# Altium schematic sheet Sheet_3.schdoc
size 307 x 219 mm
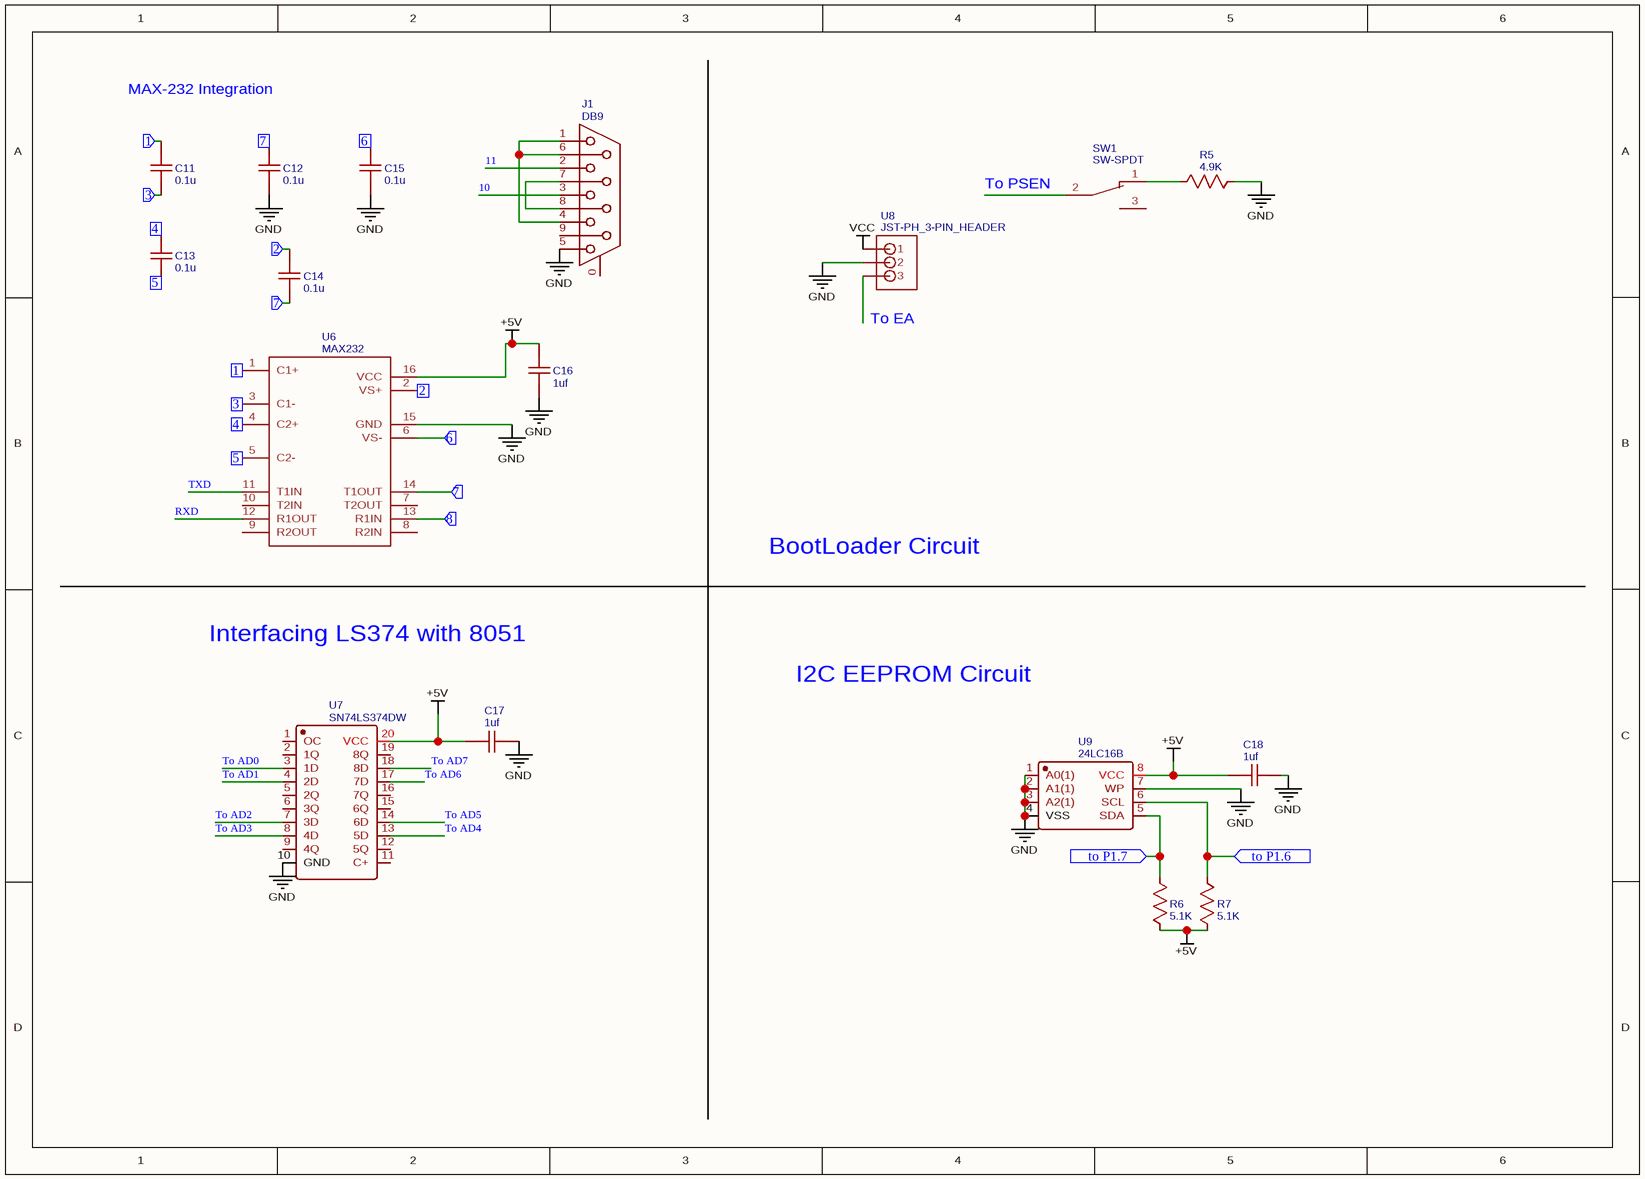
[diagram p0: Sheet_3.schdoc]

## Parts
C11  0.1u  [C0603]
C12  0.1u  [C0603]
C13  0.1u  [C0603]
C14  0.1u  [C0603]
C15  0.1u  [C0603]
C16  1uf  [C0603]
C17  1uf  [C0603]
C18  1uf  [C0603]
J1  DB9
R5  4.9K  [R0603]
R6  5.1K  [R0603]
R7  5.1K  [R0603]
SW1  SW-SPDT  [SW-SPDT-]
U6  MAX232
U7  SN74LS374DW  [SOIC-20]
U8  JST-PH_3-PIN_HEADER  [JST_B3B-PH_HEADER]
U9  24LC16B  [TSSOP-8_L4.4-W3.0-P0.65-LS6.4-BL]

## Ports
1 (in), 2 (in), 3 (in), 4 (in), 5 (in), 6 (in), 7 (in), 8 (in), to P1.6 (in), to P1.7 (in)

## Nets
+5V: C16.2 C17.1 C18.1 R6.1 R7.1 U6.16(VCC) U7.20(VCC) U9.8(VCC)
GND: C12.1 C15.1 C16.1 C17.2 C18.2 J1.5 R5.2 U6.15(GND) U7.10(GND) U8.P2(2) U9.1(A0(1)) U9.2(A1(1)) U9.3(A2(1)) U9.4(VSS) U9.7(WP)
VCC: U8.P1(1)
1: C11.2 U6.1(C1+) ; port 1
2: C14.2 U6.2(VS+) ; port 2
3: C11.1 U6.3(C1-) ; port 3
4: C13.2 U6.4(C2+) ; port 4
5: C13.1 U6.5(C2-) ; port 5
6: C15.2 U6.6(VS-) ; port 6
7: C12.2 C14.1 U6.14(T1OUT) ; port 7
8: U6.13(R1IN) ; port 8
10: J1.3
11: J1.2
RXD: U6.12(R1OUT)
To AD0: U7.3(1D)
To AD1: U7.4(2D)
To AD2: U7.7(3D)
To AD3: U7.8(4D)
To AD4: U7.13(5D)
To AD5: U7.14(6D)
To AD6: U7.17(7D)
To AD7: U7.18(8D)
to P1.6: R7.2 U9.6(SCL) ; port to P1.6
to P1.7: R6.2 U9.5(SDA) ; port to P1.7
TXD: U6.11(T1IN)
NetJ1_1: J1.1 J1.4 J1.6
NetJ1_7: J1.7 J1.8
NetR5_1: R5.1 SW1.1

Not connected (* = marked no-connect by the designer): J1 0(PAD) 9; SW1 2 3; U6 7(T2OUT) 8(R2IN) 9(R2OUT) 10(T2IN); U7 1(OC) 2(1Q) 5(2Q) 6(3Q) 9(4Q) 11(C+) 12(5Q) 15(6Q) 16(7Q) 19(8Q); U8 P3(3)

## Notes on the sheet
- MAX-232 Integration
- To PSEN
- (near U8) To EA
- BootLoader Circuit
- Interfacing LS374 with 8051
- I2C EEPROM Circuit

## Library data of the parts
C11-C15 = 0.1u: nameAlias: Value(F); Contributor: LCEDA_Lib
C16-C18 = 1uf: nameAlias: Value(F); Contributor: LCEDA_Lib
J1 = DB9: Contributor: KiCAD
R5 = 4.9K: nameAlias: Value(Ω); Contributor: LCEDA_Lib
R6 R7 = 5.1K: nameAlias: Value(Ω); Contributor: LCEDA_Lib
U9 = 24LC16B: BOM_Manufacturer: null; BOM_Manufacturer Part: 24LC16B-E/ST; Contributor: LCSC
